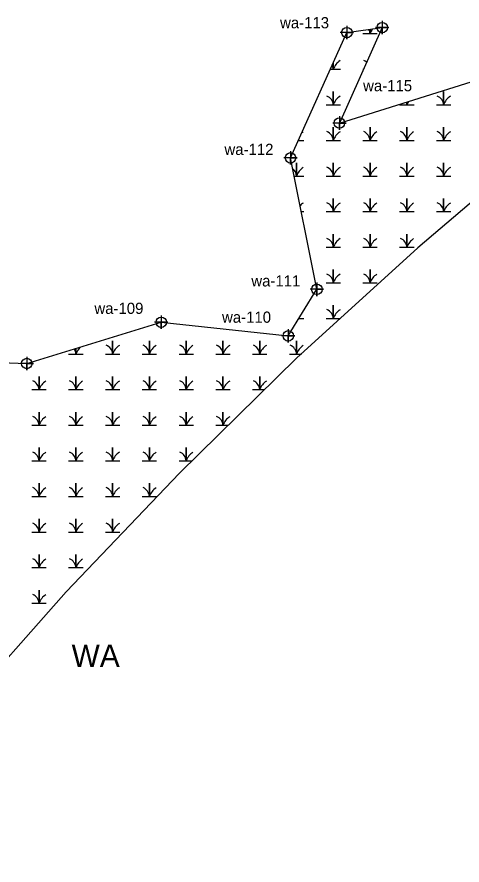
# Model space of a CAD drawing. Extents: x 2379288 to 2381905, y 330670 to 333511.
# Drawn here: x 2380693.6 to 2380892.7, y 332296.2 to 332675.4 of the extents above; entities that cross this region are included whole.
import ezdxf

# ---------------------------------------------------------------- set-up
doc = ezdxf.new("R2010")
doc.units = 0
for name, color, linetype in [('Default', 7, 'Continuous'), ('Exist Environmental Wetland Boundary', 7, 'Continuous'), ('Exist Environmental Wetland Boundary Cogo Number', 7, 'Continuous'), ('Exist Environmental Wetland Boundary Cogo Point CELL', 7, 'Continuous'), ('Exist Environmental Wetland Boundary Text', 7, 'Continuous'), ('Exist Hydro Swamp or Marsh', 7, 'Continuous')]:
    doc.layers.add(name, color=color, linetype=linetype)

msp = doc.modelspace()

# ---------------------------------------------------------------- linework, layer by layer
at = {"layer": 'Default'}
msp.add_lwpolyline([(2380928.76, 332619.64), (2380872.86, 332572.17), (2380818.67, 332522.77), (2380766.25, 332471.49), (2380715.67, 332418.4), (2380666.98, 332363.57), (2380620.25, 332307.06), (2380575.53, 332248.94), (2380532.89, 332189.29), (2380492.36, 332128.18), (2380455.21, 332067.63)], dxfattribs=at)
at = {"layer": 'Exist Environmental Wetland Boundary'}
msp.add_lwpolyline([(2380442.38, 332045.91), (2380445.79, 332068.31), (2380430.27, 332144.34), (2380463.17, 332209.13), (2380440.55, 332246.83), (2380410.07, 332261.34), (2380400.64, 332277.99), (2380430.32, 332327.14), (2380475.22, 332338.88), (2380523.99, 332375.18), (2380571.84, 332459.01), (2380602.28, 332487.78), (2380643.42, 332522.54), (2380698.01, 332520.45), (2380758.16, 332538.88), (2380814.95, 332532.8), (2380827.75, 332553.62), (2380815.96, 332612.38), (2380841.18, 332668.4), (2380857.01, 332670.65), (2380837.85, 332627.97), (2380932.82, 332657.69)], dxfattribs=at)
at = {"layer": 'Exist Environmental Wetland Boundary Cogo Point CELL'}
for points in [[(2380857.01, 332673.65), (2380857.01, 332667.65), (2380857.01, 332670.65), (2380860.01, 332670.65), (2380854.01, 332670.65)], [(2380841.18, 332671.4), (2380841.18, 332665.4), (2380841.18, 332668.4), (2380844.18, 332668.4), (2380838.18, 332668.4)], [(2380837.85, 332630.97), (2380837.85, 332624.97), (2380837.85, 332627.97), (2380840.85, 332627.97), (2380834.85, 332627.97)], [(2380815.96, 332615.38), (2380815.96, 332609.38), (2380815.96, 332612.38), (2380818.96, 332612.38), (2380812.96, 332612.38)], [(2380827.75, 332556.62), (2380827.75, 332550.62), (2380827.75, 332553.62), (2380830.75, 332553.62), (2380824.75, 332553.62)], [(2380758.16, 332541.88), (2380758.16, 332535.88), (2380758.16, 332538.88), (2380761.16, 332538.88), (2380755.16, 332538.88)], [(2380814.95, 332535.8), (2380814.95, 332529.8), (2380814.95, 332532.8), (2380817.95, 332532.8), (2380811.95, 332532.8)], [(2380698.01, 332523.45), (2380698.01, 332517.45), (2380698.01, 332520.45), (2380701.01, 332520.45), (2380695.01, 332520.45)]]:
    msp.add_lwpolyline(points, dxfattribs=at)
for centre in [(2380841.18, 332668.4), (2380857.01, 332670.65), (2380837.85, 332627.97), (2380815.96, 332612.38), (2380827.75, 332553.62), (2380758.16, 332538.88), (2380814.95, 332532.8), (2380698.01, 332520.45)]:
    msp.add_circle(centre, 2.34, dxfattribs=at)
at = {"layer": 'Exist Hydro Swamp or Marsh'}
for p, q in [((2380848.34, 332652.02), (2380848.65, 332652.02)), ((2380819.48, 332620.19), (2380821.89, 332620.19)), ((2380820.78, 332588.35), (2380821.89, 332588.35)), ((2380819.75, 332540.6), (2380821.89, 332540.6))]:
    msp.add_line(p, q, dxfattribs=at)
for points in [[(2380848.34, 332667.94), (2380851.57, 332667.94), (2380851.57, 332669.87)], [(2380851.57, 332669.87), (2380851.57, 332667.94), (2380854.79, 332667.94)], [(2380833.81, 332652.02), (2380835.12, 332652.02), (2380835.12, 332654.93)], [(2380835.12, 332654.93), (2380835.12, 332652.02), (2380838.34, 332652.02)], [(2380831.89, 332636.1), (2380835.12, 332636.1), (2380835.12, 332642.02), (2380835.12, 332636.1), (2380838.34, 332636.1)], [(2380881.24, 332636.1), (2380884.47, 332636.1), (2380884.47, 332642.02), (2380884.47, 332636.1), (2380887.7, 332636.1)], [(2380864.79, 332636.1), (2380868.02, 332636.1), (2380868.02, 332637.41)], [(2380868.02, 332637.41), (2380868.02, 332636.1), (2380871.24, 332636.1)], [(2380831.89, 332620.19), (2380835.12, 332620.19), (2380835.12, 332626.1), (2380835.12, 332620.19), (2380838.34, 332620.19)], [(2380848.34, 332620.19), (2380851.57, 332620.19), (2380851.57, 332626.1), (2380851.57, 332620.19), (2380854.79, 332620.19)], [(2380864.79, 332620.19), (2380868.02, 332620.19), (2380868.02, 332626.1), (2380868.02, 332620.19), (2380871.24, 332620.19)], [(2380881.24, 332620.19), (2380884.47, 332620.19), (2380884.47, 332626.1), (2380884.47, 332620.19), (2380887.7, 332620.19)], [(2380817.59, 332604.27), (2380818.67, 332604.27), (2380818.67, 332610.19), (2380818.67, 332604.27), (2380821.89, 332604.27)], [(2380831.89, 332604.27), (2380835.12, 332604.27), (2380835.12, 332610.19), (2380835.12, 332604.27), (2380838.34, 332604.27)], [(2380848.34, 332604.27), (2380851.57, 332604.27), (2380851.57, 332610.19), (2380851.57, 332604.27), (2380854.79, 332604.27)], [(2380864.79, 332604.27), (2380868.02, 332604.27), (2380868.02, 332610.19), (2380868.02, 332604.27), (2380871.24, 332604.27)], [(2380881.24, 332604.27), (2380884.47, 332604.27), (2380884.47, 332610.19), (2380884.47, 332604.27), (2380887.7, 332604.27)], [(2380831.89, 332588.35), (2380835.12, 332588.35), (2380835.12, 332594.27), (2380835.12, 332588.35), (2380838.34, 332588.35)], [(2380848.34, 332588.35), (2380851.57, 332588.35), (2380851.57, 332594.27), (2380851.57, 332588.35), (2380854.79, 332588.35)], [(2380864.79, 332588.35), (2380868.02, 332588.35), (2380868.02, 332594.27), (2380868.02, 332588.35), (2380871.24, 332588.35)], [(2380881.24, 332588.35), (2380884.47, 332588.35), (2380884.47, 332594.27), (2380884.47, 332588.35), (2380887.7, 332588.35)], [(2380831.89, 332572.43), (2380835.12, 332572.43), (2380835.12, 332578.35), (2380835.12, 332572.43), (2380838.34, 332572.43)], [(2380848.34, 332572.43), (2380851.57, 332572.43), (2380851.57, 332578.35), (2380851.57, 332572.43), (2380854.79, 332572.43)], [(2380864.79, 332572.43), (2380868.02, 332572.43), (2380868.02, 332578.35), (2380868.02, 332572.43), (2380871.24, 332572.43)], [(2380831.89, 332556.52), (2380835.12, 332556.52), (2380835.12, 332562.43), (2380835.12, 332556.52), (2380838.34, 332556.52)], [(2380848.34, 332556.52), (2380851.57, 332556.52), (2380851.57, 332562.43), (2380851.57, 332556.52), (2380854.79, 332556.52)], [(2380831.89, 332540.6), (2380835.12, 332540.6), (2380835.12, 332546.52), (2380835.12, 332540.6), (2380838.23, 332540.6)], [(2380733.18, 332524.68), (2380736.41, 332524.68), (2380736.41, 332530.6), (2380736.41, 332524.68), (2380739.63, 332524.68)], [(2380749.63, 332524.68), (2380752.86, 332524.68), (2380752.86, 332530.6), (2380752.86, 332524.68), (2380756.09, 332524.68)], [(2380766.09, 332524.68), (2380769.31, 332524.68), (2380769.31, 332530.6), (2380769.31, 332524.68), (2380772.54, 332524.68)], [(2380782.54, 332524.68), (2380785.76, 332524.68), (2380785.76, 332530.6), (2380785.76, 332524.68), (2380788.99, 332524.68)], [(2380798.99, 332524.68), (2380802.21, 332524.68), (2380802.21, 332530.6), (2380802.21, 332524.68), (2380805.44, 332524.68)], [(2380815.44, 332524.68), (2380818.67, 332524.68), (2380818.67, 332530.6), (2380818.67, 332524.68), (2380820.86, 332524.68)], [(2380716.73, 332524.68), (2380719.96, 332524.68), (2380719.96, 332527.18)], [(2380719.96, 332527.18), (2380719.96, 332524.68), (2380723.18, 332524.68)], [(2380700.28, 332508.76), (2380703.51, 332508.76), (2380703.51, 332514.68), (2380703.51, 332508.76), (2380706.73, 332508.76)], [(2380716.73, 332508.76), (2380719.96, 332508.76), (2380719.96, 332514.68), (2380719.96, 332508.76), (2380723.18, 332508.76)], [(2380733.18, 332508.76), (2380736.41, 332508.76), (2380736.41, 332514.68), (2380736.41, 332508.76), (2380739.63, 332508.76)], [(2380749.63, 332508.76), (2380752.86, 332508.76), (2380752.86, 332514.68), (2380752.86, 332508.76), (2380756.09, 332508.76)], [(2380766.09, 332508.76), (2380769.31, 332508.76), (2380769.31, 332514.68), (2380769.31, 332508.76), (2380772.54, 332508.76)], [(2380782.54, 332508.76), (2380785.76, 332508.76), (2380785.76, 332514.68), (2380785.76, 332508.76), (2380788.99, 332508.76)], [(2380798.99, 332508.76), (2380802.21, 332508.76), (2380802.21, 332514.68), (2380802.21, 332508.76), (2380804.36, 332508.76)], [(2380700.28, 332492.84), (2380703.51, 332492.84), (2380703.51, 332498.76), (2380703.51, 332492.84), (2380706.73, 332492.84)], [(2380716.73, 332492.84), (2380719.96, 332492.84), (2380719.96, 332498.76), (2380719.96, 332492.84), (2380723.18, 332492.84)], [(2380733.18, 332492.84), (2380736.41, 332492.84), (2380736.41, 332498.76), (2380736.41, 332492.84), (2380739.63, 332492.84)], [(2380749.63, 332492.84), (2380752.86, 332492.84), (2380752.86, 332498.76), (2380752.86, 332492.84), (2380756.09, 332492.84)], [(2380766.09, 332492.84), (2380769.31, 332492.84), (2380769.31, 332498.76), (2380769.31, 332492.84), (2380772.54, 332492.84)], [(2380782.54, 332492.84), (2380785.76, 332492.84), (2380785.76, 332498.76), (2380785.76, 332492.84), (2380788.08, 332492.84)], [(2380700.28, 332476.93), (2380703.51, 332476.93), (2380703.51, 332482.84), (2380703.51, 332476.93), (2380706.73, 332476.93)], [(2380716.73, 332476.93), (2380719.96, 332476.93), (2380719.96, 332482.84), (2380719.96, 332476.93), (2380723.18, 332476.93)], [(2380733.18, 332476.93), (2380736.41, 332476.93), (2380736.41, 332482.84), (2380736.41, 332476.93), (2380739.63, 332476.93)], [(2380749.63, 332476.93), (2380752.86, 332476.93), (2380752.86, 332482.84), (2380752.86, 332476.93), (2380756.09, 332476.93)], [(2380766.09, 332476.93), (2380769.31, 332476.93), (2380769.31, 332482.84), (2380769.31, 332476.93), (2380771.81, 332476.93)], [(2380700.28, 332461.01), (2380703.51, 332461.01), (2380703.51, 332466.93), (2380703.51, 332461.01), (2380706.73, 332461.01)], [(2380716.73, 332461.01), (2380719.96, 332461.01), (2380719.96, 332466.93), (2380719.96, 332461.01), (2380723.18, 332461.01)], [(2380733.18, 332461.01), (2380736.41, 332461.01), (2380736.41, 332466.93), (2380736.41, 332461.01), (2380739.63, 332461.01)], [(2380749.63, 332461.01), (2380752.86, 332461.01), (2380752.86, 332466.93), (2380752.86, 332461.01), (2380756.09, 332461.01)], [(2380700.28, 332445.09), (2380703.51, 332445.09), (2380703.51, 332451.01), (2380703.51, 332445.09), (2380706.73, 332445.09)], [(2380716.73, 332445.09), (2380719.96, 332445.09), (2380719.96, 332451.01), (2380719.96, 332445.09), (2380723.18, 332445.09)], [(2380733.18, 332445.09), (2380736.41, 332445.09), (2380736.41, 332451.01), (2380736.41, 332445.09), (2380739.63, 332445.09)], [(2380700.28, 332429.17), (2380703.51, 332429.17), (2380703.51, 332435.09), (2380703.51, 332429.17), (2380706.73, 332429.17)], [(2380716.73, 332429.17), (2380719.96, 332429.17), (2380719.96, 332435.09), (2380719.96, 332429.17), (2380723.18, 332429.17)], [(2380700.28, 332413.26), (2380703.51, 332413.26), (2380703.51, 332419.17), (2380703.51, 332413.26), (2380706.73, 332413.26)]]:
    msp.add_lwpolyline(points, dxfattribs=at)
for centre, radius, start, end in [((2380846.97, 332667.61), 4.61, 4.1403, 28.3734), ((2380858.41, 332665.67), 7.21, 142.7382, 161.6222), ((2380841.96, 332649.75), 7.21, 122.1274, 161.6222), ((2380846.97, 332651.69), 4.61, 48.1899, 67.535), ((2380830.52, 332651.69), 4.61, 4.1403, 27.3722), ((2380830.52, 332635.77), 4.61, 4.1403, 67.535), ((2380841.96, 332633.83), 7.21, 122.1274, 161.6222), ((2380879.87, 332635.77), 4.61, 4.1403, 67.535), ((2380891.31, 332633.83), 7.21, 122.1274, 161.6222), ((2380863.42, 332635.77), 4.61, 4.1403, 19.7234), ((2380874.86, 332633.83), 7.21, 148.1756, 161.6222), ((2380825.51, 332617.91), 7.21, 122.1274, 128.86), ((2380830.52, 332619.85), 4.61, 4.1403, 67.535), ((2380841.96, 332617.91), 7.21, 122.1274, 161.6222), ((2380846.97, 332619.85), 4.61, 4.1403, 67.535), ((2380858.41, 332617.91), 7.21, 122.1274, 161.6222), ((2380863.42, 332619.85), 4.61, 4.1403, 67.535), ((2380874.86, 332617.91), 7.21, 122.1274, 161.6222), ((2380879.87, 332619.85), 4.61, 4.1403, 67.535), ((2380891.31, 332617.91), 7.21, 122.1274, 161.6222), ((2380814.07, 332603.94), 4.61, 4.1403, 51.5531), ((2380825.51, 332602), 7.21, 122.1274, 161.6222), ((2380830.52, 332603.94), 4.61, 4.1403, 67.535), ((2380841.96, 332602), 7.21, 122.1274, 161.6222), ((2380846.97, 332603.94), 4.61, 4.1403, 67.535), ((2380858.41, 332602), 7.21, 122.1274, 161.6222), ((2380863.42, 332603.94), 4.61, 4.1403, 67.535), ((2380874.86, 332602), 7.21, 122.1274, 161.6222), ((2380879.87, 332603.94), 4.61, 4.1403, 67.535), ((2380891.31, 332602), 7.21, 122.1274, 161.6222), ((2380825.51, 332586.08), 7.21, 122.1274, 136.8181), ((2380830.52, 332588.02), 4.61, 4.1403, 67.535), ((2380841.96, 332586.08), 7.21, 122.1274, 161.6222), ((2380846.97, 332588.02), 4.61, 4.1403, 67.535), ((2380858.41, 332586.08), 7.21, 122.1274, 161.6222), ((2380863.42, 332588.02), 4.61, 4.1403, 67.535), ((2380874.86, 332586.08), 7.21, 122.1274, 161.6222), ((2380879.87, 332588.02), 4.61, 4.1403, 67.535), ((2380891.31, 332586.08), 7.21, 122.1274, 161.6222), ((2380830.52, 332572.1), 4.61, 4.1403, 67.535), ((2380841.96, 332570.16), 7.21, 122.1274, 161.6222), ((2380846.97, 332572.1), 4.61, 4.1403, 67.535), ((2380858.41, 332570.16), 7.21, 122.1274, 161.6222), ((2380863.42, 332572.1), 4.61, 4.1403, 67.535), ((2380874.86, 332570.16), 7.21, 122.1274, 161.6222), ((2380830.52, 332556.18), 4.61, 4.1403, 67.535), ((2380841.96, 332554.24), 7.21, 122.1274, 161.6222), ((2380846.97, 332556.18), 4.61, 4.1403, 67.535), ((2380858.41, 332554.24), 7.21, 122.1274, 161.6222), ((2380830.52, 332540.26), 4.61, 4.1403, 67.535), ((2380841.96, 332538.33), 7.21, 122.1274, 161.6222), ((2380715.36, 332524.35), 4.61, 4.1403, 34.14), ((2380726.8, 332522.41), 7.21, 131.468, 161.6222), ((2380731.81, 332524.35), 4.61, 4.1403, 67.535), ((2380743.25, 332522.41), 7.21, 122.1274, 161.6222), ((2380748.26, 332524.35), 4.61, 4.1403, 67.535), ((2380759.7, 332522.41), 7.21, 122.1274, 161.6222), ((2380764.71, 332524.35), 4.61, 4.1403, 67.535), ((2380776.15, 332522.41), 7.21, 122.1274, 161.6222), ((2380781.16, 332524.35), 4.61, 4.1403, 67.535), ((2380792.6, 332522.41), 7.21, 122.1274, 161.6222), ((2380797.61, 332524.35), 4.61, 4.1403, 67.535), ((2380809.05, 332522.41), 7.21, 122.1274, 161.6222), ((2380814.07, 332524.35), 4.61, 4.1403, 67.535), ((2380825.51, 332522.41), 7.21, 122.1274, 161.6222), ((2380698.91, 332508.43), 4.61, 4.1403, 67.535), ((2380710.35, 332506.49), 7.21, 122.1274, 161.6222), ((2380715.36, 332508.43), 4.61, 4.1403, 67.535), ((2380726.8, 332506.49), 7.21, 122.1274, 161.6222), ((2380731.81, 332508.43), 4.61, 4.1403, 67.535), ((2380743.25, 332506.49), 7.21, 122.1274, 161.6222), ((2380748.26, 332508.43), 4.61, 4.1403, 67.535), ((2380759.7, 332506.49), 7.21, 122.1274, 161.6222), ((2380764.71, 332508.43), 4.61, 4.1403, 67.535), ((2380776.15, 332506.49), 7.21, 122.1274, 161.6222), ((2380781.16, 332508.43), 4.61, 4.1403, 67.535), ((2380792.6, 332506.49), 7.21, 122.1274, 161.6222), ((2380797.61, 332508.43), 4.61, 4.1403, 67.535), ((2380809.05, 332506.49), 7.21, 122.1274, 161.6222), ((2380698.91, 332492.51), 4.61, 4.1403, 67.535), ((2380710.35, 332490.57), 7.21, 122.1274, 161.6222), ((2380715.36, 332492.51), 4.61, 4.1403, 67.535), ((2380726.8, 332490.57), 7.21, 122.1274, 161.6222), ((2380731.81, 332492.51), 4.61, 4.1403, 67.535), ((2380743.25, 332490.57), 7.21, 122.1274, 161.6222), ((2380748.26, 332492.51), 4.61, 4.1403, 67.535), ((2380759.7, 332490.57), 7.21, 122.1274, 161.6222), ((2380764.71, 332492.51), 4.61, 4.1403, 67.535), ((2380776.15, 332490.57), 7.21, 122.1274, 161.6222), ((2380781.16, 332492.51), 4.61, 4.1403, 67.535), ((2380792.6, 332490.57), 7.21, 122.1274, 161.6222), ((2380698.91, 332476.59), 4.61, 4.1403, 67.535), ((2380710.35, 332474.65), 7.21, 122.1274, 161.6222), ((2380715.36, 332476.59), 4.61, 4.1403, 67.535), ((2380726.8, 332474.65), 7.21, 122.1274, 161.6222), ((2380731.81, 332476.59), 4.61, 4.1403, 67.535), ((2380743.25, 332474.65), 7.21, 122.1274, 161.6222), ((2380748.26, 332476.59), 4.61, 4.1403, 67.535), ((2380759.7, 332474.65), 7.21, 122.1274, 161.6222), ((2380764.71, 332476.59), 4.61, 4.1403, 67.535), ((2380776.15, 332474.65), 7.21, 122.1274, 161.6222), ((2380698.91, 332460.68), 4.61, 4.1403, 67.535), ((2380710.35, 332458.74), 7.21, 122.1274, 161.6222), ((2380715.36, 332460.68), 4.61, 4.1403, 67.535), ((2380726.8, 332458.74), 7.21, 122.1274, 161.6222), ((2380731.81, 332460.68), 4.61, 4.1403, 67.535), ((2380743.25, 332458.74), 7.21, 122.1274, 161.6222), ((2380748.26, 332460.68), 4.61, 4.1403, 67.535), ((2380759.7, 332458.74), 7.21, 122.1274, 161.6222), ((2380698.91, 332444.76), 4.61, 4.1403, 67.535), ((2380710.35, 332442.82), 7.21, 122.1274, 161.6222), ((2380715.36, 332444.76), 4.61, 4.1403, 67.535), ((2380726.8, 332442.82), 7.21, 122.1274, 161.6222), ((2380731.81, 332444.76), 4.61, 4.1403, 67.535), ((2380743.25, 332442.82), 7.21, 122.1274, 161.6222), ((2380698.91, 332428.84), 4.61, 4.1403, 67.535), ((2380710.35, 332426.9), 7.21, 122.1274, 161.6222), ((2380715.36, 332428.84), 4.61, 4.1403, 67.535), ((2380726.8, 332426.9), 7.21, 122.1274, 161.6222), ((2380698.91, 332412.92), 4.61, 4.1403, 67.535), ((2380710.35, 332410.98), 7.21, 122.1274, 161.6222)]:
    msp.add_arc(centre, radius, start, end, dxfattribs=at)

# ---------------------------------------------------------------- texts
at = {"layer": 'Exist Environmental Wetland Boundary Cogo Number'}
for s, p in [('wa-113', (2380811.29, 332670.32)), ('wa-115', (2380848.43, 332642.18)), ('wa-112', (2380786.41, 332613.69)), ('wa-111', (2380798.44, 332554.9)), ('wa-109', (2380728.24, 332542.63)), ('wa-110', (2380785.33, 332538.67))]:
    msp.add_text(s, height=5, dxfattribs=at).set_placement(p)
at = {"layer": 'Exist Environmental Wetland Boundary Text'}
msp.add_text('WA', height=10, dxfattribs=at).set_placement((2380718.04, 332384.79))

doc.saveas('drawing.dxf')
